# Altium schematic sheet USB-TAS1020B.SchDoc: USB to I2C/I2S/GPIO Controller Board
size 431 x 279 mm; Date: Not shown in title block; ApprovedBy: Not shown in title block; CheckedBy: Not shown in title block; Author: Not shown in title block; CompanyName: Not shown in title block; DrawnBy: LDN; Engineer: Not shown in title block; Organization: Not shown in title block; Address1: Not shown in title block; Address2: Not shown in title block; Address3: Not shown in title block; Address4: Not shown in title block; DocumentNumber: 1; Revision: A; SheetNumber: 1; SheetTotal: 3; PageSetup: Record=PageOptions¦CenterHorizontal=True¦CenterVertical=True¦PrintScale=0.98¦XCorrection=1.00¦YCorrection=1.00¦PrintKind=0¦BorderSize=5000000¦LeftOffset=0¦BottomOffset=0¦Orientation=2¦PaperLength=1000¦PaperWidth=1000¦Scale=100¦PaperSource=15¦PrintQuality=-3¦MediaType=1¦DitherType=10¦PrintScaleMode=1¦PaperKind=11 x 17¦PaperIndex=119
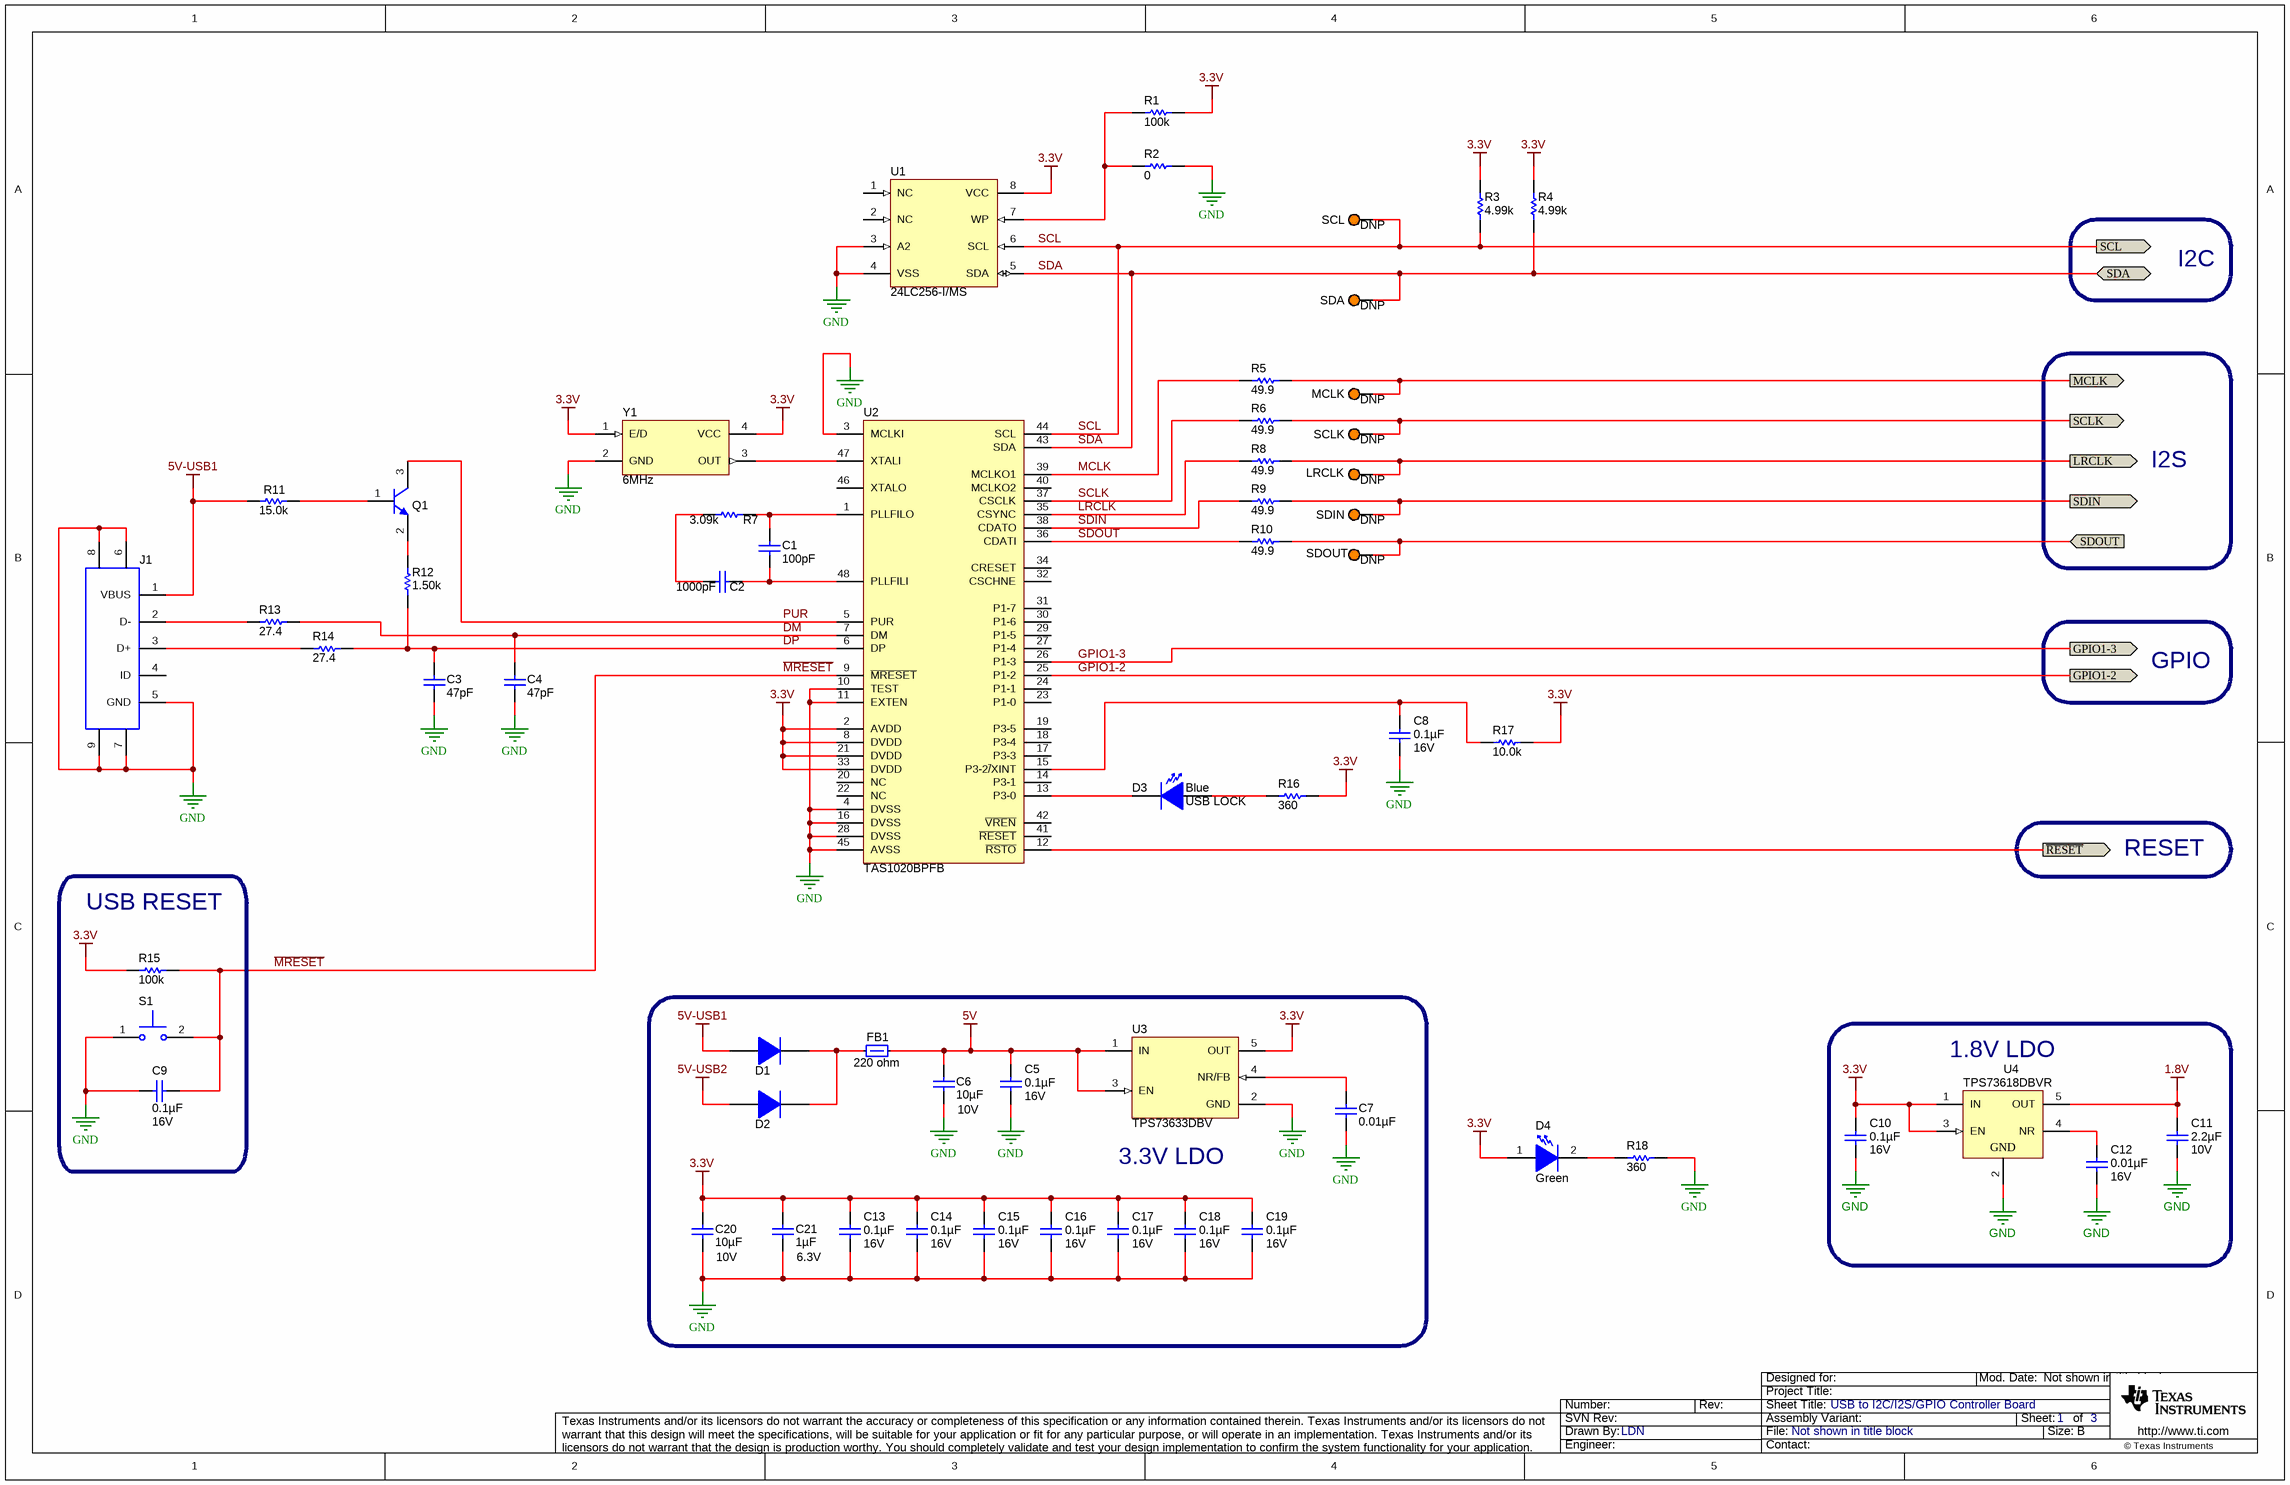
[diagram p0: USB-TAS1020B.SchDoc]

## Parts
C1  ValueDisplayed: 100pF  [0402L]  (hidden comment: GRM1555C1H101JA01D)
C2  ValueDisplayed: 1000pF  [0402L]  (hidden comment: GRM1555C1H102JA01D)
C3  ValueDisplayed: 47pF  [0402L]  (hidden comment: GRM1555C1E470JA01D)
C4  ValueDisplayed: 47pF  [0402L]  (hidden comment: GRM1555C1E470JA01D)
C5  ValueDisplayed: 0.1µF  Value2: 16V  [0402L]  (hidden comment: GRM155R71C104KA88D)
C6  ValueDisplayed: 10µF  Value2: 10V  [0603L]  (hidden comment: C1608X5R1A106M)
C7  ValueDisplayed: 0.01µF  [0402L]  (hidden comment: C1005X7R1C103K)
C8  ValueDisplayed: 0.1µF  Value2: 16V  [0402L]  (hidden comment: GRM155R71C104KA88D)
C9  ValueDisplayed: 0.1µF  Value2: 16V  [0402L]  (hidden comment: GRM155R71C104KA88D)
C10  ValueDisplayed: 0.1µF  Value2: 16V  [0402L]  (hidden comment: GRM155R71C104KA88D)
C11  ValueDisplayed: 2.2µF  Value2: 10V  [0603]  (hidden comment: GRM188R71A225KE15D)
C12  ValueDisplayed: 0.01µF  Value2: 16V  [0402L]  (hidden comment: C1005X7R1C103K)
C13  ValueDisplayed: 0.1µF  Value2: 16V  [0402L]  (hidden comment: GRM155R71C104KA88D)
C14  ValueDisplayed: 0.1µF  Value2: 16V  [0402L]  (hidden comment: GRM155R71C104KA88D)
C15  ValueDisplayed: 0.1µF  Value2: 16V  [0402L]  (hidden comment: GRM155R71C104KA88D)
C16  ValueDisplayed: 0.1µF  Value2: 16V  [0402L]  (hidden comment: GRM155R71C104KA88D)
C17  ValueDisplayed: 0.1µF  Value2: 16V  [0402L]  (hidden comment: GRM155R71C104KA88D)
C18  ValueDisplayed: 0.1µF  Value2: 16V  [0402L]  (hidden comment: GRM155R71C104KA88D)
C19  ValueDisplayed: 0.1µF  Value2: 16V  [0402L]  (hidden comment: GRM155R71C104KA88D)
C20  ValueDisplayed: 10µF  Value2: 10V  [0603L]  (hidden comment: C1608X5R1A106M)
C21  ValueDisplayed: 1µF  Value2: 6.3V  [0402L]  (hidden comment: C1005X5R0J105M)
D1  ES1A-13-F  [SMA]  (value not drawn)
D2  ES1A-13-F  [SMA]  (value not drawn)
D3  USB LOCK  value Blue  [LED_SMLP12_BLUE]
D4  value Green  [LED_LTST-C171]  (hidden comment: LTST-C171GKT)
FB1  value 220 ohm  [0603]  (hidden comment: MPZ1608S221A)
J1  DX4R205JJAR1800  [CONN_USB_DX4R205JJA]  (value not drawn)
LRCLK  DNP  [Keystone5003]
MCLK  DNP  [Keystone5003]
Q1  MMBT2222A  [SOT-23]  (value not drawn)
R1  value 100k  [0402L]  (hidden comment: CRCW0402100KFKED)
R2  ValueDisplayed: 0  [0603L]  (hidden comment: CRCW06030000Z0EA)
R3  value 4.99k  [0402L]  (hidden comment: CRCW04024K99FKED)
R4  value 4.99k  [0402L]  (hidden comment: CRCW04024K99FKED)
R5  value 49.9  [0402L]  (hidden comment: CRCW040249R9FKED)
R6  value 49.9  [0402L]  (hidden comment: CRCW040249R9FKED)
R7  value 3.09k  [0402L]  (hidden comment: CRCW04023K09FKED)
R8  value 49.9  [0402L]  (hidden comment: CRCW040249R9FKED)
R9  value 49.9  [0402L]  (hidden comment: CRCW040249R9FKED)
R10  value 49.9  [0402L]  (hidden comment: CRCW040249R9FKED)
R11  value 15.0k  [0402L]  (hidden comment: CRCW040215K0FKED)
R12  value 1.50k  [0402L]  (hidden comment: CRCW04021K50FKED)
R13  value 27.4  [0402L]  (hidden comment: CRCW040227R4FKED)
R14  value 27.4  [0402L]  (hidden comment: CRCW040227R4FKED)
R15  value 100k  [0402L]  (hidden comment: CRCW0402100KFKED)
R16  value 360  [0402L]  (hidden comment: CRCW0402360RJNED)
R17  ValueDisplayed: 10.0k  [0402L]  (hidden comment: CRCW040210K0FKED)
R18  value 360  [0402L]  (hidden comment: CRCW0402360RJNED)
S1  TL1015AF160QG  [SW_TL1015AF160QG]  (value not drawn)
SCL  DNP  [Keystone5003]
SCLK  DNP  [Keystone5003]
SDA  DNP  [Keystone5003]
SDIN  DNP  [Keystone5003]
SDOUT  DNP  [Keystone5003]
U1  24LC256-I/MS  [SOP65P490X110-8_N]
U2  TAS1020BPFB  [PFB0048A_N]
U3  TPS73633DBV  [DBV0005A_N]
U4  TPS73618DBVR  [DBV0005A_N]
Y1  Frequency: 6MHz  [OSC_CTS_625]  (hidden comment: 625L3I006M00000)

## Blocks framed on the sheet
USB RESET: C9 R15 S1
3.3V LDO: C5-C7 C13-C21 D1 D2 FB1 U3
1.8V LDO: C10-C12 U4

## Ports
GPIO1-2 (out), GPIO1-3 (out), LRCLK (out), MCLK (out), SCL (out), SCLK (out), SDA (bidir), SDIN (out), SDOUT (in), ~{RESET} (out)

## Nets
1.8V: C11.2 U4.5(OUT)
3.3V: C10.1 C13.1 C14.1 C15.1 C16.1 C17.1 C18.1 C19.1 C20.1 C21.2 D4.1(A) R1.2 R3.2 R4.2 R15.1 R16.1 R17.2 U1.8(VCC) U2.2(AVDD) U2.8(DVDD) U2.21(DVDD) U2.33(DVDD) U3.5(OUT) U4.1(IN) U4.3(EN) Y1.1(E/D) Y1.4(VCC)
5V: C5.1 C6.1 FB1.2 U3.1(IN) U3.3(EN)
5V-USB1: D1.2(A) J1.1(VBUS) R11.1
5V-USB2: D2.2(A)
GND: C3.1 C4.1 C5.2 C6.2 C7.2 C8.2 C9.1 C10.2 C11.1 C12.2 C13.2 C14.2 C15.2 C16.2 C17.2 C18.2 C19.2 C20.2 C21.1 J1.5(GND) J1.6 J1.7 J1.8 J1.9 R2.2 R18.2 S1.1 U1.3(A2) U1.4(VSS) U2.3(MCLKI) U2.4(DVSS) U2.10(TEST) U2.11(EXTEN) U2.16(DVSS) U2.28(DVSS) U2.45(AVSS) U3.2(GND) U4.2(GND) Y1.2(GND)
~{MRESET}: C9.2 R15.2 S1.2 U2.9(~{MRESET})
~{RESET}: U2.12(~{RSTO}) ; port ~{RESET}
DM: C4.2 R13.2 U2.7(DM)
DP: C3.2 R12.2 R14.2 U2.6(DP)
GPIO1-2: U2.25(P1-2) ; port GPIO1-2
GPIO1-3: U2.26(P1-3) ; port GPIO1-3
LRCLK: LRCLK.1 R8.2 ; port LRCLK
LRCLK: R8.1 U2.35(CSYNC)  [a separate net that carries the same name]
MCLK: MCLK.1 R5.2 ; port MCLK
MCLK: R5.1 U2.39(MCLKO1)  [a separate net that carries the same name]
PUR: Q1.3(C) U2.5(PUR)
SCL: R3.1 SCL.1 U1.6(SCL) U2.44(SCL) ; port SCL
SCLK: R6.2 SCLK.1 ; port SCLK
SCLK: R6.1 U2.37(CSCLK)  [a separate net that carries the same name]
SDA: R4.1 SDA.1 U1.5(SDA) U2.43(SDA) ; port SDA
SDIN: R9.2 SDIN.1 ; port SDIN
SDIN: R9.1 U2.38(CDATO)  [a separate net that carries the same name]
SDOUT: R10.2 SDOUT.1 ; port SDOUT
SDOUT: R10.1 U2.36(CDATI)  [a separate net that carries the same name]
NetC1_1: C1.1 R7.2 U2.1(PLLFILO)
NetC1_2: C1.2 C2.1 U2.48(PLLFILI)
NetC2_2: C2.2 R7.1
NetC7_1: C7.1 U3.4(NR/FB)
NetC8_1: C8.1 R17.1 U2.15(P3-2~{/}XINT)
NetC12_1: C12.1 U4.4(NR)
NetD1_1: D1.1(K) D2.1(K) FB1.1
NetD3_1: D3.1(A) R16.2
NetD3_2: D3.2(K) U2.13(P3-0)
NetD4_2: D4.2(K) R18.1
NetJ1_2: J1.2(D-) R13.1
NetJ1_3: J1.3(D+) R14.1
NetQ1_1: Q1.1(B) R11.2
NetQ1_2: Q1.2(E) R12.1
NetR1_1: R1.1 R2.1 U1.7(WP)
NetU2_47: U2.47(XTALI) Y1.3(OUT)

Not connected (* = marked no-connect by the designer): J1 4(ID); U1 1(NC) 2(NC); U2 14(P3-1) 17(P3-3) 18(P3-4) 19(P3-5) 20(NC) 22(NC) 23(P1-0) 24(P1-1) 27(P1-4) 29(P1-5) 30(P1-6) 31(P1-7) 32(CSCHNE) 34(CRESET) 40(MCLKO2) 41(~{RESET}) 42(~{VREN}) 46(XTALO)

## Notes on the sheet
- I2C
- I2S
- GPIO
- RESET

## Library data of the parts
C1 = GRM1555C1H101JA01D: CAP, CERM, 100pF, 50V, +/-5%, C0G/NP0, 0402; Manufacturer: MuRata; Polarized: N; CompType: Capacitor; U/M: EA; Cap_F: 0.0000000001; Tolerance_%: 5; Value1: Unknown; VDC_V: 50; TaMin_C: -55; TaMax_C: 125; Cap_Case: 0402
C2 = GRM1555C1H102JA01D: CAP, CERM, 1000pF, 50V, +/-5%, C0G/NP0, 0402; Manufacturer: MuRata; Polarized: N; CompType: Capacitor; U/M: EA; Cap_F: 0.000000001; Tolerance_%: 5; Value1: Unknown; VDC_V: 50; TaMin_C: -55; TaMax_C: 125; Cap_Case: 0402
C3 C4 = GRM1555C1E470JA01D: CAP, CERM, 47pF, 25V, +/-5%, C0G/NP0, 0402; Manufacturer: MuRata; Polarized: N; CompType: Capacitor; U/M: EA; Cap_F: 0.000000000047; Tolerance_%: 5; Value1: Unknown; VDC_V: 25; TaMin_C: -55; TaMax_C: 125; Cap_Case: 0402
C5 C8-C10 C13-C19 = GRM155R71C104KA88D: CAP, CERM, 0.1uF, 16V, +/-10%, X7R, 0402; Manufacturer: MuRata; Polarized: N; CompType: Capacitor; U/M: EA; Cap_F: 0.0000001; Tolerance_%: 10; Value1: Unknown; VDC_V: 16; TaMin_C: -55; TaMax_C: 125; Cap_Case: 0402
C6 C20 = C1608X5R1A106M: CAP, CERM, 10uF, 10V, +/-20%, X5R, 0603; Manufacturer: TDK; Polarized: N; CompType: Capacitor; U/M: EA; Cap_F: 0.00001; Tolerance_%: 20; ESR_Ohm: 0.0078; Value1: 0.0078 ohm; VDC_V: 10; IRMS_A: 1.85; TaMin_C: -55; TaMax_C: 85; Cap_Case: 0603
C7 C12 = C1005X7R1C103K: CAP, CERM, 0.01uF, 16V, +/-10%, X7R, 0402; Manufacturer: TDK; Polarized: N; CompType: Capacitor; U/M: EA; Cap_F: 0.00000001; Tolerance_%: 10; ESR_Ohm: 0.0623; Value1: 0.0623 ohm; VDC_V: 16; TaMin_C: -55; TaMax_C: 125; Cap_Case: 0402
C11 = GRM188R71A225KE15D: CAP, CERM, 2.2 µF, 10 V, +/- 10%, X7R, 0603; Manufacturer: MuRata; Polarized: N; CompType: Capacitor; Value: 2.2uF; U/M: EA; Cap_F: 0.0000022; Tolerance_%: 10; ESR_ohm: 0.009; Value1: 0.009 ohm; TaMin_C: -55; TaMax_C: 125
C21 = C1005X5R0J105M: CAP, CERM, 1uF, 6.3V, +/-20%, X5R, 0402; Manufacturer: TDK; Polarized: N; CompType: Capacitor; U/M: EA; Cap_F: 0.000001; Tolerance_%: 20; ESR_Ohm: 0.0079; Value1: 0.0079 ohm; VDC_V: 6.3; TaMin_C: -55; TaMax_C: 85; Cap_Case: 0402
D1 D2 = ES1A-13-F: Diode, Ultrafast, 50 V, 1 A, SMA; Manufacturer: Diodes Inc.; U/M: EA; Vf_V: 0.88; Value: 50V; Value1: 1A; Value2: 0.88V; Io_A: 1; Vr_V: 50
D3 = SMLP12BC7TT86: LED, Blue, SMD; Manufacturer: Rohm; Type: InGaN; Vf_V: 2.9; Value2: 2.9V; Io_A: 0.005; Tjmax_C: 85; Value1: W; U/M: EA
D4 = LTST-C171GKT: LED, Green, SMD; Manufacturer: Lite-On; Type: AlInGaP; Vf_V: 2.1; Value2: 2.1V; Io_A: 20; Value1: W; U/M: EA
FB1 = MPZ1608S221A: 2.2A Ferrite Bead, 220 ohm @ 100MHz, SMD; Manufacturer: TDK; Imax_A: 2.2; DCR_ohm: 0.05; Value1: 0.05 ohm; ZTyp@100MHz_Ohm: 220; U/M: EA
J1 = DX4R205JJAR1800: Connector, Receptacle, Micro-USB Type AB, R/A, Bottom Mount SMT; Manufacturer: JAE Electronics; SymbolCreator: a0799628; U/M: EA
LRCLK MCLK SCL SCLK SDA SDIN SDOUT = 5003: Test Point, Miniature, Orange, TH; Manufacturer: Keystone; CompType: Test Point Loop; U/M: EA
Q1 = MMBT2222A, Fairchild Semiconductor: Transistor, NPN, 40V, 0.15A, SOT-23; CompType: BJT; PNP: 0; NPN: 1; Vceo_V: 40; Vcesat1_V: 0.3; Value: 0.3V; IcRated_A: 0.15; HfeMax: 300; TaMin_C: -55; TaMax_C: 150; U/M: EA
R1 R15 = CRCW0402100KFKED: RES, 100k ohm, 1%, 0.063W, 0402; Manufacturer: Vishay-Dale; CompType: Resistor; Res_ohm: 100000; Tolerance_%: 1; Power_W: 0.063; VDC_V: 50; TempCo: 100 ppm/C; EIA_Code: E96; U/M: EA
R2 = CRCW06030000Z0EA: RES, 0, 5%, 0.1 W, 0603; Manufacturer: Vishay-Dale; CompType: Resistor; Value: 0; Value_Code: 0000; Tolerance_%: 5; Power_W: 0.1; Value2: 0.1W; VDC_V: 75; TempCo: 200 ppm/C; EIA_Code: E24; U/M: EA
R3 R4 = CRCW04024K99FKED: RES, 4.99k ohm, 1%, 0.063W, 0402; Manufacturer: Vishay-Dale; CompType: Resistor; Res_ohm: 4990; Value_Code: 4k99; Tolerance_%: 1; Power_W: 0.063; VDC_V: 50; TempCo: 100 ppm/C; EIA_Code: E96; U/M: EA
R5 R6 R8-R10 = CRCW040249R9FKED: RES, 49.9 ohm, 1%, 0.063W, 0402; Manufacturer: Vishay-Dale; CompType: Resistor; Value_Code: 49R9; Tolerance_%: 1; Power_W: 0.063; VDC_V: 50; TempCo: 100 ppm/C; EIA_Code: E96; U/M: EA
R7 = CRCW04023K09FKED: RES, 3.09k ohm, 1%, 0.063W, 0402; Manufacturer: Vishay-Dale; CompType: Resistor; Res_ohm: 3090; Value_Code: 3k09; Tolerance_%: 1; Power_W: 0.063; VDC_V: 50; TempCo: 100 ppm/C; EIA_Code: E96; U/M: EA
R11 = CRCW040215K0FKED: RES, 15.0k ohm, 1%, 0.063W, 0402; Manufacturer: Vishay-Dale; CompType: Resistor; Res_ohm: 15000; Value_Code: 15k0; Tolerance_%: 1; Power_W: 0.063; VDC_V: 50; TempCo: 100 ppm/C; EIA_Code: E96; U/M: EA
R12 = CRCW04021K50FKED: RES, 1.50k ohm, 1%, 0.063W, 0402; Manufacturer: Vishay-Dale; CompType: Resistor; Res_ohm: 1500; Value_Code: 1k50; Tolerance_%: 1; Power_W: 0.063; VDC_V: 50; TempCo: 100 ppm/C; EIA_Code: E96; U/M: EA
R13 R14 = CRCW040227R4FKED: RES, 27.4 ohm, 1%, 0.063W, 0402; Manufacturer: Vishay-Dale; CompType: Resistor; Value_Code: 27R4; Tolerance_%: 1; Power_W: 0.063; VDC_V: 50; TempCo: 100 ppm/C; EIA_Code: E96; U/M: EA
R16 R18 = CRCW0402360RJNED: RES, 360 ohm, 5%, 0.063W, 0402; Manufacturer: Vishay-Dale; CompType: Resistor; Value_Code: 360R; Tolerance_%: 5; Power_W: 0.063; VDC_V: 50; TempCo: 200 ppm/C; EIA_Code: E24; U/M: EA
R17 = CRCW040210K0FKED: RES, 10.0 k, 1%, 0.063 W, 0402; Manufacturer: Vishay-Dale; CompType: Resistor; Value: 10.0k; Res_ohm: 10000; Value_Code: 10k0; Tolerance_%: 1; Power_W: 0.063; Value2: 0.063W; VDC_V: 50; TempCo: 100 ppm/C; EIA_Code: E96; U/M: EA
S1 = TL1015AF160QG: Switch, Tactile, SPST-NO, 0.05A, 12V, SMT; Manufacturer: E-Switch; SymbolCreator: a0412235; VDC_V: 12; SwitchFunction: Off-Mom; PositionCount: 1; CurrentRating_mA: 50
U1 = 24LC256-I/MS: EEPROM, 256KBIT, 400KHZ, MSOP8; Manufacturer: Microchip; SymbolCreator: a0411947
U2 = TAS1020BPFB: IC, USB Streaming Controller; Manufacturer: TI; Alternate Manufacturer: None; Area: 178084
U3 = TPS73633DBV: Cap-Free, NMOS, 400mA Low-Dropout Regulator with Reverse Current Protection, DBV0005A; Alternate Manufacturer: None; Manufacturer: Texas Instruments; SymbolCreator: a0411947; CompType: IC; U/M: EA
U4 = TPS73618DBVR: Single Output Low Noise LDO, 400 mA, Fixed 1.8 V Output, 1.7 to 5.5 V Input, with Reverse Current Protection, 5-pin SOT-23 (DBV), -40 to 85 degC, Green (RoHS & no Sb/Br); Manufacturer: Texas Instruments; Alternate Manufacturer: None; Alternate PartNumber: Equivalent; Accuracy(%): 1; Fixed Output Options(V): 1.8; Iout(Max)(A): 0.4; Iq(Typ)(mA): 0.3; Rating: Catalog; SubFamily: Single Channel LDO; Vdo(Typ)(mV): 75; Vin(Max)(V): 5.5; Vin(Min)(V): 1.7
Y1 = 625L3I006M00000: Oscillator, 6MHz, 3.3V, SMD; Manufacturer: CTS Electrocomponents; SymbolCreator: a0411947; U/M: EA; TaMin_C: -40; TaMax_C: 85; Frequency Stability: ±50ppm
